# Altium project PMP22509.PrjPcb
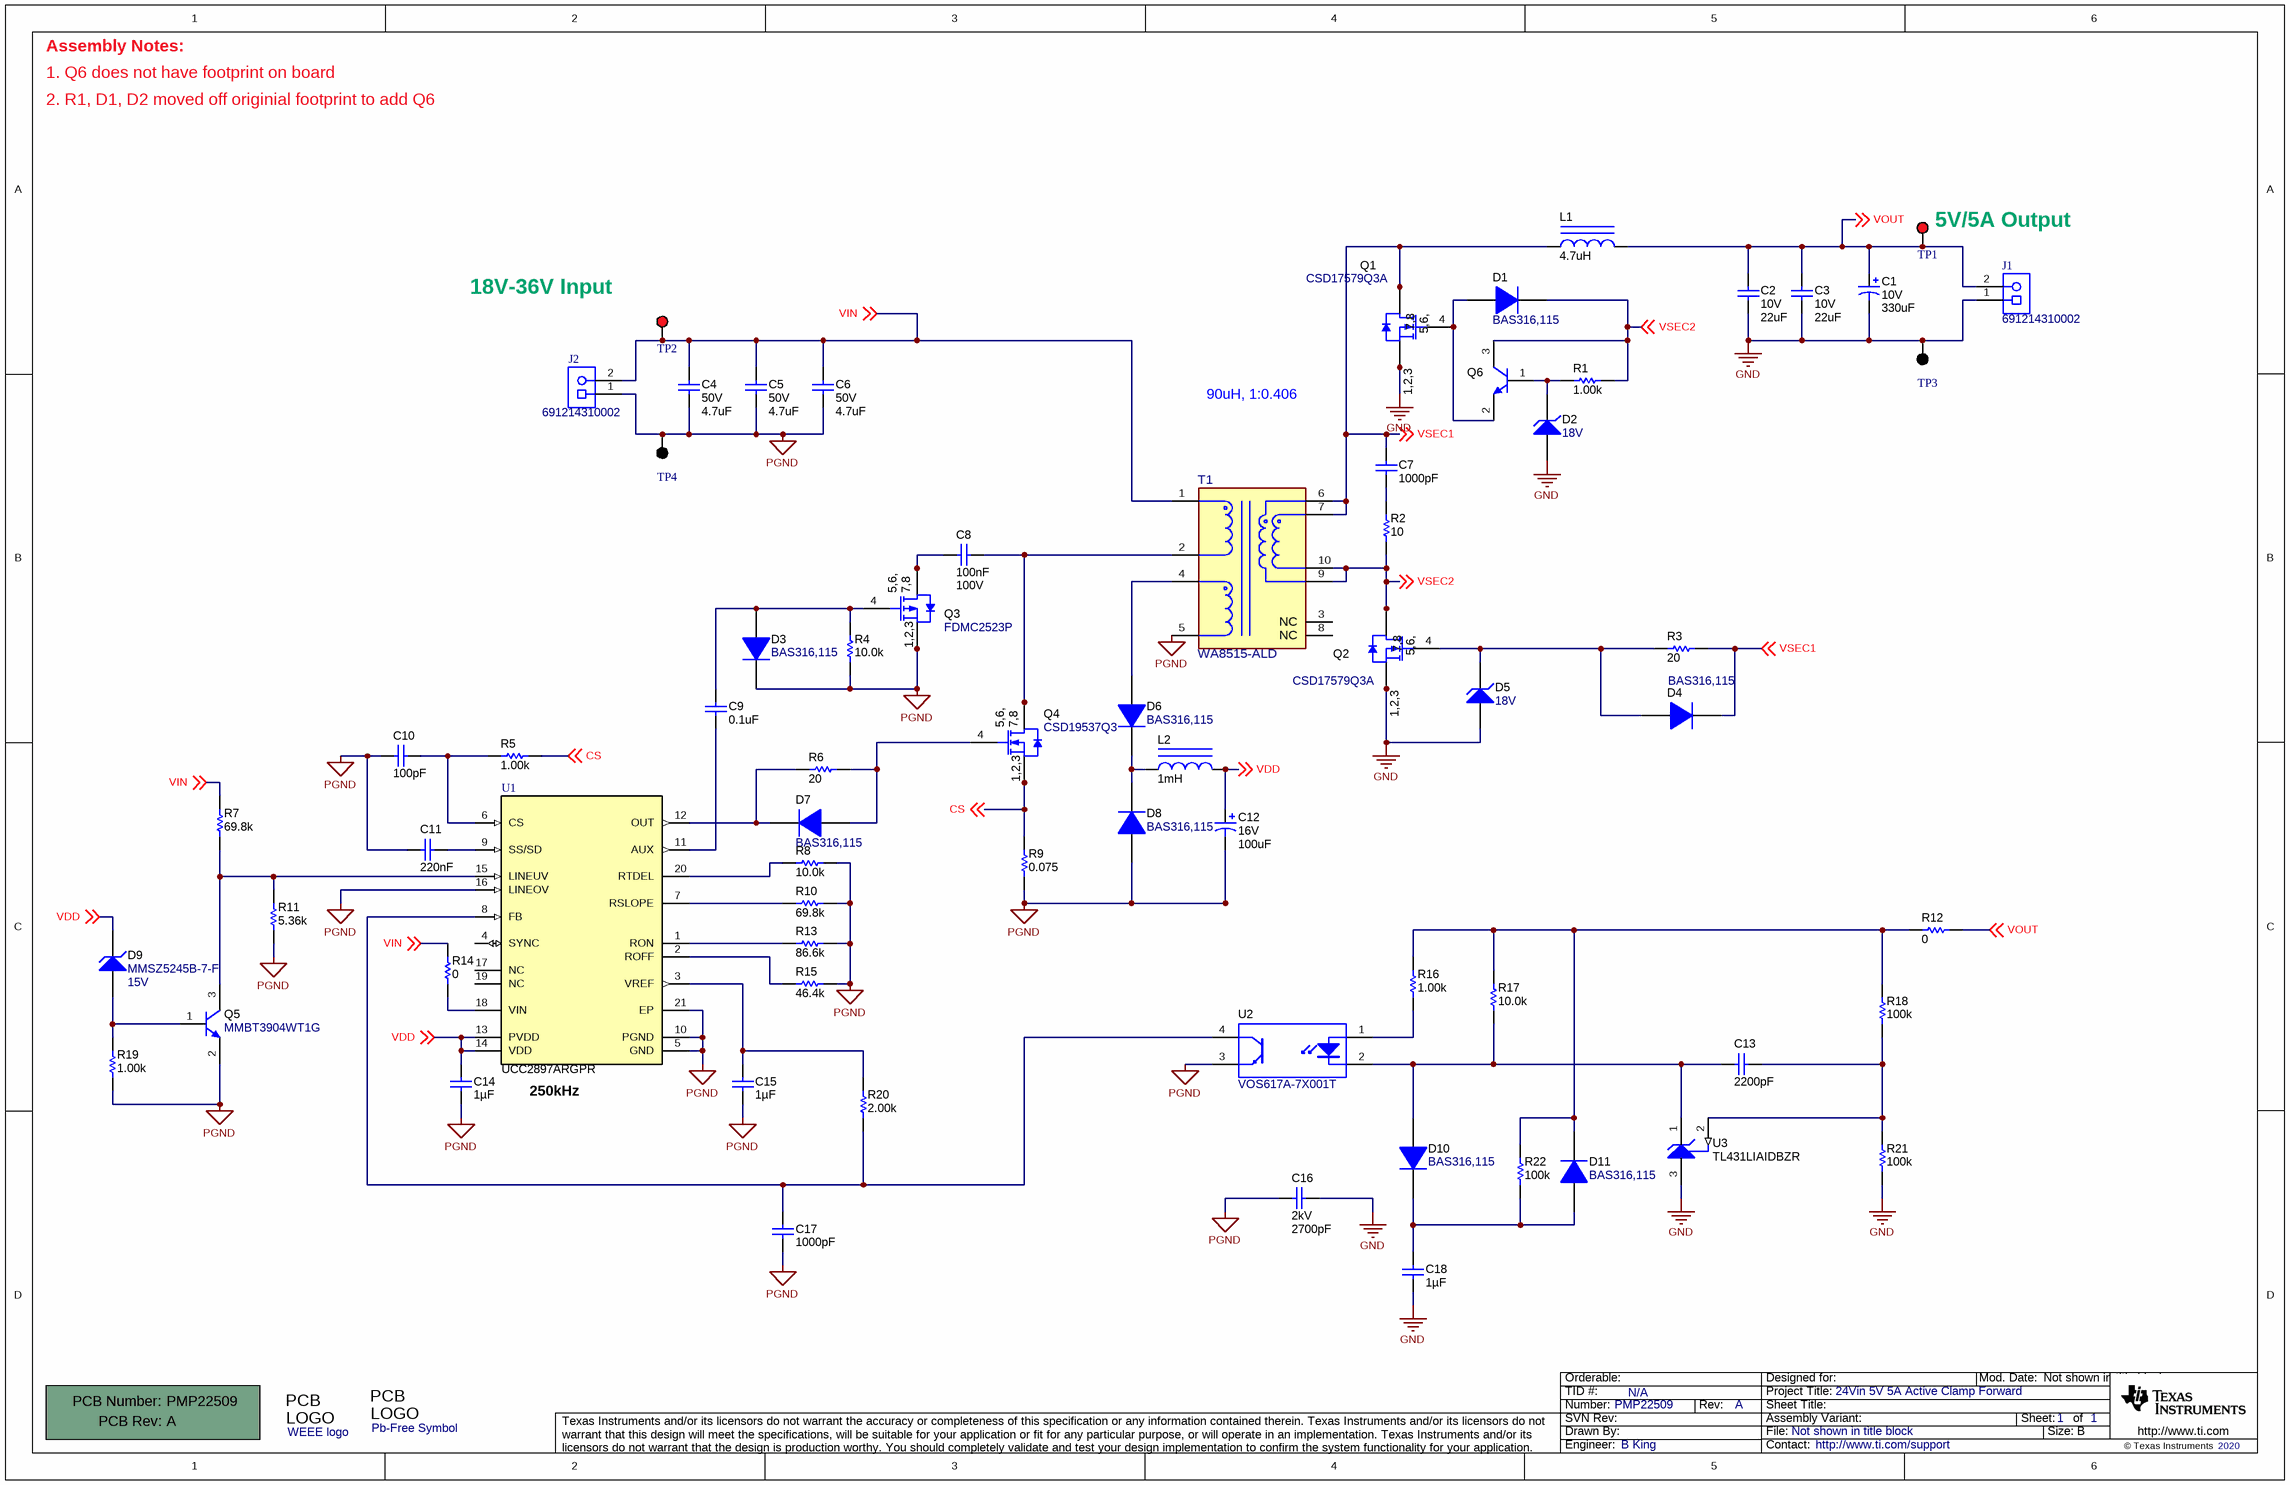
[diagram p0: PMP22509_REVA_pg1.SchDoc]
TID: N/A; TechSupport: http://www.ti.com/support; SCH_Rev: A; PRJ_Title: 24Vin 5V 5A Active Clamp Forward; PRJ_Number: PMP22509; PRJ_Engineer: B King; PCB_Rev: A; PCB_Layout: B King; CopyrightYear: 2020
1 sheet, 72 parts. Net scope: global (net labels, ports and power ports of the same name join across sheets).
Board file: PMP22509_REVA_PCB.PcbDoc

## Sheet PMP22509_REVA_pg1.SchDoc
size 431 x 279 mm; Date: Not shown in title block; ApprovedBy: Not shown in title block; CheckedBy: Not shown in title block; Author: Not shown in title block; CompanyName: Not shown in title block; Engineer: Not shown in title block; Organization: Not shown in title block; Address1: Not shown in title block; Address2: Not shown in title block; Address3: Not shown in title block; Address4: Not shown in title block; DocumentNumber: 1; Revision: Use project parameter SCH_Rev; SheetNumber: 1; SheetTotal: 1; PageSetup: Record=PageOptions¦CenterHorizontal=True¦CenterVertical=True¦PrintScale=1.00¦XCorrection=1.00¦YCorrection=1.00¦PrintKind=0¦BorderSize=5000000¦LeftOffset=0¦BottomOffset=0¦Orientation=2¦PaperLength=1000¦PaperWidth=1000¦Scale=100¦PaperSource=15¦PrintQuality=600¦MediaType=1¦DitherType=10¦PaperKind=Letter¦PrintScaleMode=1

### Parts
!PCB1  Printed Circuit Board  (value not drawn)  (mechanical)
C1  VDC_V: 10V  ValueDisplayed: 330uF  [ZLH_630x1100]  (hidden comment: 10ZLH330MEFC6.3X11)
C2  VDC_V: 10V  ValueDisplayed: 22uF  [1206_180]  (hidden comment: GRM31CR71A226KE15L)
C3  VDC_V: 10V  ValueDisplayed: 22uF  [1206_180]  (hidden comment: GRM31CR71A226KE15L)
C4  VDC_V: 50V  ValueDisplayed: 4.7uF  [1206_180]  (hidden comment: C3216X7R1H475K160AC)
C5  VDC_V: 50V  ValueDisplayed: 4.7uF  [1206_180]  (hidden comment: C3216X7R1H475K160AC)
C6  VDC_V: 50V  ValueDisplayed: 4.7uF  [1206_180]  (hidden comment: C3216X7R1H475K160AC)
C7  ValueDisplayed: 1000pF  [0402]  (hidden comment: CGA2B2X7R1H102K050BA)
C8  Cap_F: 100nF  VDC_V: 100V  [0805_HV]  (hidden comment: GRM21BR72A104KAC4L)
C9  ValueDisplayed: 0.1uF  [0402]  (hidden comment: GRM155R71E104KE14D)
C10  ValueDisplayed: 100pF  [0402]  (hidden comment: GRM1555C1H101JA01D)
C11  Cap_F: 220nF  [0603]  (hidden comment: C1608X7R1H224K080AB)
C12  VDC_V: 16V  ValueDisplayed: 100uF  [Chemi-Con_500x1100]  (hidden comment: EKMG160ELL101ME11D)
C13  ValueDisplayed: 2200pF  [0402]  (hidden comment: GRM155R71H222KA01D)
C14  Cap_F: 1µF  [0603]  (hidden comment: CGA3E1X7R1V105K080AE)
C15  Cap_F: 1µF  [0603]  (hidden comment: CGA3E1X7R1V105K080AE)
C16  VDC_V: 2kV  ValueDisplayed: 2700pF  [1808]  (hidden comment: C1808C272KGRACTU)
C17  ValueDisplayed: 1000pF  [0402]  (hidden comment: CGA2B2X7R1H102K050BA)
C18  Cap_F: 1µF  [0603]  (hidden comment: CGA3E1X7R1V105K080AE)
D1  BAS316,115  [SOD-323]
D2  value 18V  [SOD-323]  (hidden comment: SZMM3Z18VST1G)
D3  BAS316,115  [SOD-323]
D4  BAS316,115  [SOD-323]
D5  value 18V  [SOD-323]  (hidden comment: SZMM3Z18VST1G)
D6  BAS316,115  [SOD-323]
D7  BAS316,115  [SOD-323]
D8  BAS316,115  [SOD-323]
D9  MMSZ5245B-7-F  value 15V  [SOD-123]
D10  BAS316,115  [SOD-323]
D11  BAS316,115  [SOD-323]
J1  691214310002  [Wurth_691214310002]
J2  691214310002  [Wurth_691214310002]
L1  ValueDisplayed: 4.7uH  [MSS1278T]  (hidden comment: MSS1278T-472MLB)
L2  ValueDisplayed: 1mH  [LPS4414]  (hidden comment: LPS4414-105MLB)
Logo1  Pb-Free Symbol  [Pb-Free_Overlay_Medium]  (no BOM)
Logo2  WEEE logo  [WEEE_Minimum]  (no BOM)
Q1  CSD17579Q3A  [DNH0008A]
Q2  CSD17579Q3A  [DNH0008A]
Q3  FDMC2523P  [MLP08S]
Q4  CSD19537Q3  [DQG0008A]
Q5  MMBT3904WT1G  [SOT-323]
Q6  FMMT495TA  [SOT-23]  (value not drawn)
R1  ValueDisplayed: 1.00k  [0402]  (hidden comment: MCR01MZPF1001)
R2  ValueDisplayed: 10  [1206]  (hidden comment: CRCW120610R0JNEA)
R3  ValueDisplayed: 20  [0402]  (hidden comment: CRCW040220R0JNED)
R4  ValueDisplayed: 10.0k  [0402]  (hidden comment: CRCW040210K0FKED)
R5  ValueDisplayed: 1.00k  [0402]  (hidden comment: CRCW04021K00FKED)
R6  ValueDisplayed: 20  [0402]  (hidden comment: CRCW040220R0JNED)
R7  ValueDisplayed: 69.8k  [0402]  (hidden comment: CRCW040269K8FKED)
R8  ValueDisplayed: 10.0k  [0402]  (hidden comment: CRCW040210K0FKED)
R9  ValueDisplayed: 0.075  [1206]  (hidden comment: CSR1206FK75L0)
R10  ValueDisplayed: 69.8k  [0402]  (hidden comment: CRCW040269K8FKED)
R11  ValueDisplayed: 5.36k  [0402]  (hidden comment: CRCW04025K36FKED)
R12  ValueDisplayed: 0  [0402]  (hidden comment: CRCW04020000Z0ED)
R13  ValueDisplayed: 86.6k  [0402]  (hidden comment: CRCW040286K6FKED)
R14  ValueDisplayed: 0  [0402]  (hidden comment: CRCW04020000Z0ED)
R15  ValueDisplayed: 46.4k  [0402]  (hidden comment: CRCW040246K4FKED)
R16  ValueDisplayed: 1.00k  [0402]  (hidden comment: CRCW04021K00FKED)
R17  ValueDisplayed: 10.0k  [0402]  (hidden comment: CRCW040210K0FKED)
R18  ValueDisplayed: 100k  [0402]  (hidden comment: CRCW0402100KFKED)
R19  ValueDisplayed: 1.00k  [0402]  (hidden comment: CRCW04021K00FKED)
R20  ValueDisplayed: 2.00k  [0402]  (hidden comment: CRCW04022K00FKED)
R21  ValueDisplayed: 100k  [0402]  (hidden comment: CRCW0402100KFKED)
R22  ValueDisplayed: 100k  [0402]  (hidden comment: CRCW0402100KFKED)
T1  WA8515-ALD  [FP-WA8515-ALD_SMT_TRANSFORMER_13MM00_13MM46-MFG]
TP1  5010  [Keystone5010]  (value not drawn)
TP2  5010  [Keystone5010]  (value not drawn)
TP3  5011  [Keystone5011]  (value not drawn)
TP4  5011  [Keystone5011]  (value not drawn)
U1  UCC2897ARGPR  [RGP0020D]
U2  VOS617A-7X001T  [SSOP-4_VISHAY]
U3  TL431LIAIDBZR  [DBZ0003A_N]

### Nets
GND: C1.2(-) C2.2 C3.2 C16.1 C18.1 D2.2(A) D5.2(A) J1.1 Q1.1(S) Q1.2(S) Q1.3(S) Q2.1(S) Q2.2(S) Q2.3(S) R21.1 TP3.1 U3.3(ANODE)
PGND: C4.2 C5.2 C6.2 C10.1 C11.2 C12.2(-) C14.1 C15.1 C16.2 C17.2 D3.1(K) D8.2(A) J2.1 Q3.1(S) Q3.2(S) Q3.3(S) Q5.2(E) R4.2 R8.2 R9.1 R10.2 R11.2 R13.2 R15.2 R19.1 T1.5 TP4.1 U1.5(GND) U1.10(PGND) U1.16(LINEOV) U1.21(EP) U2.3(E)
CS: Q4.1(S) Q4.2(S) Q4.3(S) R5.2 R9.2 ; off-sheet CS
VDD: C12.1(+) C14.2 D9.1(K) L2.2 U1.13(PVDD) U1.14(VDD) ; off-sheet VDD
VIN: C4.1 C5.1 C6.1 J2.2 R7.1 R14.1 T1.1 TP2.1 ; off-sheet VIN
VOUT: C1.1(+) C2.1 C3.1 J1.2 L1.2 R12.1 TP1.1 ; off-sheet VOUT
VSEC1: C7.1 D4.1(K) L1.1 Q1.5(D) Q1.6(D) Q1.7(D) Q1.8(D) Q1.9(D) R3.2 T1.6 T1.7 ; off-sheet VSEC1
VSEC2: D1.1(K) Q2.5(D) Q2.6(D) Q2.7(D) Q2.8(D) Q2.9(D) Q6.3(C) R1.2 R2.1 T1.9 T1.10 ; off-sheet VSEC2
NetC7_2: C7.2 R2.2
NetC8_1: C8.1 Q4.5(D) Q4.6(D) Q4.7(D) Q4.8(D) Q4.9(D) T1.2
NetC8_2: C8.2 Q3.5(D) Q3.6(D) Q3.7(D) Q3.8(D)
NetC9_1: C9.1 U1.11(AUX)
NetC9_2: C9.2 D3.2(A) Q3.4(G) R4.1
NetC10_2: C10.2 R5.1 U1.6(CS)
NetC11_1: C11.1 U1.9(SS/SD)
NetC13_1: C13.1 R18.1 R21.2 U3.2(REF)
NetC13_2: C13.2 D10.2(A) R17.1 U2.2(K) U3.1(CATHODE)
NetC15_2: C15.2 R20.1 U1.3(VREF)
NetC17_1: C17.1 R20.2 U1.8(FB) U2.4(C)
NetC18_2: C18.2 D10.1(K) D11.2(A) R22.1
NetD1_2: D1.2(A) Q1.4(G) Q6.2(E)
NetD2_1: D2.1(K) Q6.1(B) R1.1
NetD4_2: D4.2(A) D5.1(K) Q2.4(G) R3.1
NetD6_1: D6.1(K) D8.1(K) L2.1
NetD6_2: D6.2(A) T1.4
NetD7_1: D7.1(K) R6.1 U1.12(OUT)
NetD7_2: D7.2(A) Q4.4(G) R6.2
NetD9_2: D9.2(A) Q5.1(B) R19.2
NetD11_1: D11.1(K) R12.2 R16.2 R17.2 R18.2 R22.2
NetQ5_3: Q5.3(C) R7.2 R11.1 U1.15(LINEUV)
NetR8_1: R8.1 U1.20(RTDEL)
NetR10_1: R10.1 U1.7(RSLOPE)
NetR13_1: R13.1 U1.1(RON)
NetR14_2: R14.2 U1.18(VIN)
NetR15_1: R15.1 U1.2(ROFF)
NetR16_1: R16.1 U2.1(A)

Not connected (* = marked no-connect by the designer): T1 3(NC) 8(NC); U1 4(SYNC) 17(NC) 19(NC)

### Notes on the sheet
- Assembly Notes:
- 1. Q6 does not have footprint on board
- 2. R1, D1, D2 moved off originial footprint to add Q6
- (near TP1) 5V/5A Output
- 18V-36V Input
- 90uH, 1:0.406
- (near U1) 250kHz

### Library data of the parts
!PCB1 = PCB: Manufacturer: Any; PartNumber: PMP22509; SymbolCreator: a0412235
C1 = CMP-0010285-1: CAP, AL, 330 uF, 10 V, +/- 20%, 0.094 ohm, TH; Manufacturer: Rubycon; TaMin_C: -40°C; ESR_ohm: 0.094; Polarized: Y; SizeAreaWB_mm2: 68.89; U/M: EA; Value: 330uF; TaMax_C: 105°C; SizeZ_mm: 12.5; SizeX_mm: 6.3; Cap_Case: 6.3x11mm; CompType: Capacitor; Cap_F: 330µF; IRMS_A: 540mA; AEC Category: Q200; SizeArea_mm2: 39.69
C2 C3 = CMP-0008959-2: CAP, CERM, 22 uF, 10 V, +/- 10%, X7R, 1206; Manufacturer: MuRata; TaMin_C: -55°C; Polarized: N; SizeAreaWB_mm2: 10.92; Value1: Unknown; U/M: EA; Value: 22uF; TaMax_C: 125°C; SizeZ_mm: 1.8; SizeX_mm: 3.2; SizeY_mm: 1.6; Cap_Case: 1206; SizeArea_mm2: 5.12; Cap_F: 22µF; AEC Category: Q200
C4-C6 = CMP-0008702-2: CAP, CERM, 4.7 uF, 50 V, +/- 10%, X7R, 1206; Manufacturer: TDK; TaMin_C: -55°C; ESR_ohm: 3.158m; Polarized: N; SizeAreaWB_mm2: 10.92; Value1: 0.003158 ohm; U/M: EA; Value: 4.7uF; TaMax_C: 125°C; SizeZ_mm: 1.8; SizeX_mm: 3.2; SizeY_mm: 1.6; SizeArea_mm2: 5.12; Cap_F: 4.7µF; IRMS_A: 4.08379A; AEC Category: Q200
C7 C17 = CMP-0006314-2: CAP, CERM, 1000 pF, 50 V, +/- 10%, X7R, AEC-Q200 Grade 1, 0402; Manufacturer: TDK; TaMin_C: -55°C; ESR_ohm: 2.25564; Polarized: N; SizeAreaWB_mm2: 3; Value1: 2.25564 ohm; U/M: EA; Value: 1000pF; TaMax_C: 125°C; SizeZ_mm: 0.6; SizeX_mm: 1; SizeY_mm: 0.5; Value2: 50V; AEC Qualified: Y; Cap_F: 1nF; IRMS_A: 280.466mA; AEC Category: Q200
C8 = CMP-0008363-2: CAP, CERM, 0.1 uF, 100 V, +/- 10%, X7R, 0805; Manufacturer: MuRata; TaMin_C: -55°C; Polarized: N; SizeAreaWB_mm2: 6.75; Value1: Unknown; U/M: EA; Value: 0.1uF; TaMax_C: 125°C; SizeZ_mm: 1.45; SizeX_mm: 2; SizeY_mm: 1.25; Cap_Case: 0805; SizeArea_mm2: 2.5; AEC Category: Q200
C9 = CMP-0006659-2: CAP, CERM, 0.1 uF, 25 V, +/- 10%, X7R, 0402; Manufacturer: MuRata; TaMin_C: -55°C; Polarized: N; SizeAreaWB_mm2: 3; Value1: Unknown; U/M: EA; Value: 0.1uF; TaMax_C: 125°C; SizeZ_mm: 0.6; SizeX_mm: 1; SizeY_mm: 0.5; Value2: 25V; Cap_F: 100nF; AEC Category: Q200
C10 = CMP-0006410-2: CAP, CERM, 100 pF, 50 V, +/- 5%, C0G/NP0, 0402; Manufacturer: MuRata; TaMin_C: -55°C; Polarized: N; SizeAreaWB_mm2: 3; Value1: Unknown; U/M: EA; Value: 100pF; TaMax_C: 125°C; SizeZ_mm: 0.6; SizeX_mm: 1; SizeY_mm: 0.5; Value2: 50V; AEC Category: Q200
C11 = CMP-0007047-4: CAP, CERM, 0.22 uF, 50 V, +/- 10%, X7R, 0603; Manufacturer: TDK; TaMin_C: -55°C; ESR_ohm: 0.021699; Polarized: N; SizeAreaWB_mm2: 4.68; Value1: 0.021699 ohm; U/M: EA; Value: 0.22uF; TaMax_C: 125°C; SizeZ_mm: 1; SizeX_mm: 1.6; SizeY_mm: 0.8; Value2: 50V; SizeArea_mm2: 1.28; IRMS_A: 1.12496A; AEC Category: Q200
C12 = CMP-0010359-1: CAP, AL, 100 uF, 16 V, +/- 20%, TH; Manufacturer: Chemi-Con; TaMin_C: -55°C; Polarized: Y; SizeAreaWB_mm2: 49; Value1: Unknown; U/M: EA; Value: 100uF; TaMax_C: 105°C; SizeZ_mm: 12.5; SizeX_mm: 5; Cap_Case: 5x11mm; SizeArea_mm2: 25; CompType: Capacitor; AEC Qualified: N; Cap_F: 100µF; IRMS_A: 110mA; AEC Category: Q200
C13 = CMP-0006683-2: CAP, CERM, 2200 pF, 50 V, +/- 10%, X7R, 0402; Manufacturer: MuRata; TaMin_C: -55°C; Polarized: N; SizeAreaWB_mm2: 3; Value1: Unknown; U/M: EA; Value: 2200pF; TaMax_C: 125°C; SizeZ_mm: 0.6; SizeX_mm: 1; SizeY_mm: 0.5; Value2: 50V; Cap_F: 2.2nF; AEC Category: Q200
C14 C15 C18 = CMP-0081259-1: CAP, CERM, 1 µF, 35 V,+/- 10%, X7R, AEC-Q200 Grade 1, 0603; Manufacturer: TDK; SizeAreaWB_mm2: 4.68; SizeArea_mm2: 1.28; AEC Qualified: Y; AEC Category: Q200; Value: 1uF; TaMax_C: 125°C; SizeZ_mm: 1; Polarized: N; TaMin_C: -55°C; VDC_V: 35V; SizeY_mm: 0.8; U/M: EA; SizeX_mm: 1.6
C16 = CMP-0009316-2: CAP, CERM, 2700 pF, 2000 V, +/- 10%, X7R, 1808; Manufacturer: Kemet; TaMin_C: -55°C; Polarized: N; SizeAreaWB_mm2: 16.5; Value1: Unknown; U/M: EA; Value: 2700pF; TaMax_C: 125°C; SizeZ_mm: 2.03; SizeX_mm: 4.5; SizeY_mm: 2; Value2: 2000V; SizeArea_mm2: 9; Cap_F: 2.7nF; AEC Category: Q200
D1 D3 D4 D6-D8 D10 D11 = CMP-0029006-2: Diode, Ultrafast, 100 V, 0.25 A, SOD-323; Manufacturer: Nexperia; SizeY_mm: 1.35; Value1: 0.25A; SizeAreaWB_mm2: 8.695; SizeZ_mm: 1; Io_A: 250mA; Value2: 1.4V; SizeX_mm: 2.7; Green_REACh: Incomplete; TJmax_C: 150°C; Green_Lifecycle: Not Set; Vr_V: 100V; AEC Category: Q101; Value: 100V; SizeArea_mm2: 3.645
D2 D5 = CMP-0085765-1: Diode, Zener, 18 V, 300 mW, AEC-Q101, SOD-323; Manufacturer: ON Semiconductor; Value1: 0.3W; SizeX_mm: 2.7; RJA_CperW: 416; SizeArea_mm2: 3.645; AEC Category: Q101; SizeZ_mm: 1; Power_W: 300mW; AEC Qualified: Y; SizeY_mm: 1.35; SizeAreaWB_mm2: 8.695
D9 = CMP-0005753-4: Diode, Zener, 15 V, 500 mW, SOD-123; Manufacturer: Diodes Inc.; RJA_CperW: 350; SizeX_mm: 3.85; SizeArea_mm2: 6.545; SizeZ_mm: 1.35; Value1: 0.5W; Power_W: 500mW; SizeAreaWB_mm2: 13.095; AEC Category: Q101; SizeY_mm: 1.7
J1 J2 = CMP-0054822-2: Terminal Block, 2x1, 3.81mm, 24-16 AWG, 10A, 300VAC, TH; Manufacturer: Wurth Elektronik; CT: TRUE; CNHeader: FALSE; Green_Lifecycle: Active; Green_REACh: Passed
L1 = CMP-0060643-1: Inductor, Shielded Drum Core, Ferrite, 4.7 uH, 6.2 A, 0.01 ohm, SMD; Manufacturer: Coilcraft; Isat: 17.76A @ 30% inductance drop; Irms: 6.2A @ 40C rise; Green_Lifecycle: Not Set; SizeAreaWB_mm2: 196; DCR_ohm: 0.01; Green_REACh: Incomplete; Value: 4.7uH; Imax_A: 6.2A; SizeZ_mm: 8; SizeX_mm: 12; SizeArea_mm2: 144; Ind_H: 4.7µH; AEC Category: Q200
L2 = CMP-0061792-2: Inductor, Shielded Drum Core, Ferrite, 1 mH, 0.11 A, 16.3 ohm, SMD; Manufacturer: Coilcraft; Isat: 0.106A @ 30% inductance drop; Irms: 0.13A @ 40C rise; Green_Lifecycle: Not Set; SizeAreaWB_mm2: 28.09; DCR_ohm: 16.3; Green_REACh: Incomplete; Value: 1mH; Imax_A: 110mA; SizeZ_mm: 1.4; SizeX_mm: 4.3; Value2: 0.11A; SizeArea_mm2: 18.49; AEC Category: Q200
Logo1 = CMP-0074839-1: SymbolCreator: a0412235
Logo2 = CMP-0074769-1
Q1 Q2 = CMP-0000593-2: MOSFET, N-CH, 30 V, 20 A, DNH0008A (VSONP-8); Alternate Manufacturer: None; Manufacturer: Texas Instruments; SizeZ_mm: 0.9; ChType: N; Value2: 5.3 nC; Value1: 0.014; VdsMax_V: 30V; SizeX_mm: 3.3; Vgs_V: 20V; Value: 30V; Rdson45_ohm: 0.0142; SizeArea_mm2: 10.89; AEC Category: Q101; IdsMax_A: 20A; SizeAreaWB_mm2: 18.49; QgTyp_nC: 5.3; ChMode: Enhancement
Q3 = CMP-0000056-3: MOSFET, P-CH, -150 V, -3 A, QFN-8; Alternate Manufacturer: None; Manufacturer: Fairchild Semiconductor; ChType: P; VdsMax_V: -150V; AEC Category: Q101; Value2: 6.2 nC; SizeAreaWB_mm2: 18.49; QgTyp_nC: 6.2; Value: -150V; SizeZ_mm: 0.8; ChMode: Enhancement; AEC Qualified: N; IdsMax_A: -3A; SizeX_mm: 3.3; SizeArea_mm2: 10.89; Vgs_V: -30V
Q4 = CMP-0000967-2: MOSFET, N-CH, 100 V, 50 A, DQG0008A (VSON-CLIP-8); Alternate Manufacturer: None; Manufacturer: Texas Instruments; SizeZ_mm: 1.1; ChType: N; Value2: 16 nC; VdsMax_V: 100V; SizeX_mm: 3.3; Vgs_V: 20V; QgTyp_nC: 16; Value: 100V; SizeArea_mm2: 10.89; AEC Category: Q101; IdsMax_A: 50A; SizeAreaWB_mm2: 18.49; U/M: EA
Q5 = CMP-0000404-1: Transistor, NPN, 40 V, 0.2 A, SOT-323; Manufacturer: ON Semiconductor; TaMax_C: 150°C; Value2: 300; Value1: 0.2 A; Vcesat1_V: 300mV; SizeX_mm: 2.2; TaMin_C: -55°C; IcRated_A: 200mA; CompType: BJT; SizeZ_mm: 1.1; Value: 40 V; SizeArea_mm2: 4.84; NPN: 1; Vceo_V: 40V; PNP: 0; AEC Category: Q101; SizeAreaWB_mm2: 10.24; U/M: EA
Q6 = CMP-0074710-1: Transistor, NPN, 150 V, 1 A, AEC-Q101, SOT-23; Manufacturer: Diodes Inc.; TaMin_C: -55°C; HfeMax: 300.0; SizeAreaWB_mm2: 14.0; Value1: 1 A; Vceo_V: 150V; U/M: EA; Value: 150 V; TaMax_C: 150°C; IcRated_A: 1A; SizeZ_mm: 1.1; SizeX_mm: 2.5; SizeY_mm: 3.0; SizeArea_mm2: 7.5; CompType: BJT; PNP: 0.0; AEC Qualified: Y; NPN: 1.0; Vcesat1_V: 300mV; AEC Category: Q101
R1 = CMP-0026716-1: RES, 1.00 k, 1%, 0.063 W, 0402; Manufacturer: Rohm; Power_W: 63mW; TempCo: 100 ppm/C; Value_Code: 1k00; U/M: EA; Value: 1.00k; EIA_Code: E96; Res_ohm: 1k; SizeX_mm: 1; SizeY_mm: 0.5; SizeZ_mm: 0.6; Value2: 0.063W; AEC Qualified: N; VDC_V: 50V; AEC Category: Q200
R2 = CMP-0018578-3: RES, 10, 5%, 0.25 W, AEC-Q200 Grade 0, 1206; Manufacturer: Vishay-Dale; Power_W: 250mW; TempCo: 200 ppm/C; Value_Code: 10R0; Value: 10; EIA_Code: E24; SizeX_mm: 3.2; SizeY_mm: 1.6; SizeZ_mm: 1.35; Value2: 0.25W; SizeArea_mm2: 5.12; AEC Qualified: Y; VDC_V: 200V; AEC Category: Q200; AEC Grade: 0
R3 R6 = CMP-0026876-3: RES, 20, 5%, 0.063 W, AEC-Q200 Grade 0, 0402; Manufacturer: Vishay-Dale; Power_W: 63mW; TempCo: 200 ppm/C; Value_Code: 20R0; Value: 20; EIA_Code: E24; SizeX_mm: 1; SizeY_mm: 0.5; SizeZ_mm: 0.6; Value2: 0.063W; AEC Qualified: Y; VDC_V: 50V; AEC Category: Q200; AEC Grade: 0
R4 R8 R17 = CMP-0025958-3: RES, 10.0 k, 1%, 0.063 W, AEC-Q200 Grade 0, 0402; Manufacturer: Vishay-Dale; Power_W: 63mW; TempCo: 100 ppm/C; Value_Code: 10k0; Value: 10.0k; EIA_Code: E96; Res_ohm: 10k; SizeX_mm: 1; SizeY_mm: 0.5; SizeZ_mm: 0.6; Value2: 0.063W; AEC Qualified: Y; VDC_V: 50V; AEC Category: Q200; AEC Grade: 0
R5 R16 R19 = CMP-0026071-3: RES, 1.00 k, 1%, 0.063 W, AEC-Q200 Grade 0, 0402; Manufacturer: Vishay-Dale; Power_W: 63mW; TempCo: 100 ppm/C; Value_Code: 1k00; Value: 1.00k; EIA_Code: E96; Res_ohm: 1k; SizeX_mm: 1; SizeY_mm: 0.5; SizeZ_mm: 0.6; Value2: 0.063W; AEC Qualified: Y; VDC_V: 50V; AEC Category: Q200; AEC Grade: 0
R7 R10 = CMP-0026510-2: RES, 69.8 k, 1%, 0.063 W, AEC-Q200 Grade 0, 0402; Manufacturer: Vishay-Dale; Power_W: 63mW; TempCo: 100 ppm/C; Value_Code: 69k8; Value: 69.8k; EIA_Code: E96; SizeX_mm: 1; SizeY_mm: 0.5; SizeZ_mm: 0.6; Value2: 0.063W; AEC Qualified: Y; VDC_V: 50V; AEC Category: Q200; AEC Grade: 0
R9 = CMP-0017264-2: RES, 0.075, 1%, 0.5 W, 1206; Manufacturer: Stackpole Electronics Inc; Power_W: 500mW; TempCo: 100 ppm/C; Value_Code: R075; U/M: EA; Value: 0.075; EIA_Code: E96; SizeX_mm: 3.2; SizeY_mm: 1.6; SizeZ_mm: 1.35; Value2: 0.5W; SizeArea_mm2: 5.12; AEC Category: Q200
R11 = CMP-0026465-2: RES, 5.36 k, 1%, 0.063 W, AEC-Q200 Grade 0, 0402; Manufacturer: Vishay-Dale; Power_W: 63mW; TempCo: 100 ppm/C; Value_Code: 5k36; Value: 5.36k; EIA_Code: E96; SizeX_mm: 1; SizeY_mm: 0.5; SizeZ_mm: 0.6; Value2: 0.063W; AEC Qualified: Y; VDC_V: 50V; AEC Category: Q200; AEC Grade: 0
R12 R14 = CMP-0026822-3: RES, 0, 5%, 0.063 W, AEC-Q200 Grade 0, 0402; Manufacturer: Vishay-Dale; Power_W: 63mW; TempCo: 200 ppm/C; Value_Code: 0000; Value: 0; EIA_Code: E24; SizeX_mm: 1; SizeY_mm: 0.5; SizeZ_mm: 0.6; Value2: 0.063W; AEC Qualified: Y; VDC_V: 50V; AEC Category: Q200
R13 = CMP-0026582-2: RES, 86.6 k, 1%, 0.063 W, AEC-Q200 Grade 0, 0402; Manufacturer: Vishay-Dale; Power_W: 63mW; TempCo: 100 ppm/C; Value_Code: 86k6; Value: 86.6k; EIA_Code: E96; SizeX_mm: 1; SizeY_mm: 0.5; SizeZ_mm: 0.6; Value2: 0.063W; AEC Qualified: Y; VDC_V: 50V; AEC Category: Q200; AEC Grade: 0
R15 = CMP-0026391-2: RES, 46.4 k, 1%, 0.063 W, AEC-Q200 Grade 0, 0402; Manufacturer: Vishay-Dale; Power_W: 63mW; TempCo: 100 ppm/C; Value_Code: 46k4; Value: 46.4k; EIA_Code: E96; SizeX_mm: 1; SizeY_mm: 0.5; SizeZ_mm: 0.6; Value2: 0.063W; AEC Qualified: Y; VDC_V: 50V; AEC Category: Q200; AEC Grade: 0
R18 R21 R22 = CMP-0025950-3: RES, 100 k, 1%, 0.063 W, AEC-Q200 Grade 0, 0402; Manufacturer: Vishay-Dale; Power_W: 63mW; TempCo: 100 ppm/C; Value: 100k; EIA_Code: E96; SizeX_mm: 1; SizeY_mm: 0.5; SizeZ_mm: 0.6; Value2: 0.063W; AEC Qualified: Y; VDC_V: 50V; AEC Category: Q200; AEC Grade: 0
R20 = CMP-0026227-2: RES, 2.00 k, 1%, 0.063 W, AEC-Q200 Grade 0, 0402; Manufacturer: Vishay-Dale; Power_W: 63mW; TempCo: 100 ppm/C; Value_Code: 2k00; Value: 2.00k; EIA_Code: E96; Res_ohm: 2k; SizeX_mm: 1; SizeY_mm: 0.5; SizeZ_mm: 0.6; Value2: 0.063W; AEC Qualified: Y; VDC_V: 50V; AEC Category: Q200; AEC Grade: 0
T1 = CMP-0088844-1: 25 W Forward Mode Transformer  for TPS23754; Manufacturer: Coilcraft; AEC Qualified: No; Voltage_Isolation_Vrms: 1500Vrms; TaMax_C: +85°C; Ind_H: 90µH; DCR_ohm: 0.146; Ns1toNp: 1:0.406; TaMin_C: -40°C; Rsec1_ohm: 0.025; SizeZ_mm: 12.7mm
TP1 TP2 = CMP-0055147-1: Test Point, Multipurpose, Red, TH; Manufacturer: Keystone; CNHeader: FALSE; Green_Lifecycle: Active; Green_REACh: Passed; ContactFinish: Silver; CT: TRUE
TP3 TP4 = CMP-0055148-1: Test Point, Multipurpose, Black, TH; Manufacturer: Keystone; CNHeader: FALSE; Green_Lifecycle: Active; Green_REACh: Passed; ContactFinish: Silver; CT: TRUE
U1 = CMP-0031996-2: Advanced Active Clamp PWM Controller with Current Control, -40 to +125 degC, 20-pin QFN (RGP), Green (RoHS & no Sb/Br); Manufacturer: Texas Instruments; Frequency(Max)(kHz): 1000; Regulated Outputs(#): 1; Rating: Catalog
U2 = CMP-0006163-3: Optocoupler, 3.75 kV, 80-160% CTR, SMT; Manufacturer: Vishay-Semiconductor; CTR (Max): 160%; CTR (Min): 80%; Voltage_Isolation_Vrms: 3.75kV
U3 = CMP-0084729-1: Programmable Shunt Regulator with Optimized Reference Current, DBZ0003A (SOT-23-3); Manufacturer: Texas Instruments; SizeY_mm: 3; SizeZ_mm: 1.12; SizeX_mm: 2.5; SizeAreaWB_mm2: 14; CompType: IC; AEC Qualified: N; AEC Category: Q200; SizeArea_mm2: 7.5

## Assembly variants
001: not fitted FID1 FID2 FID3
